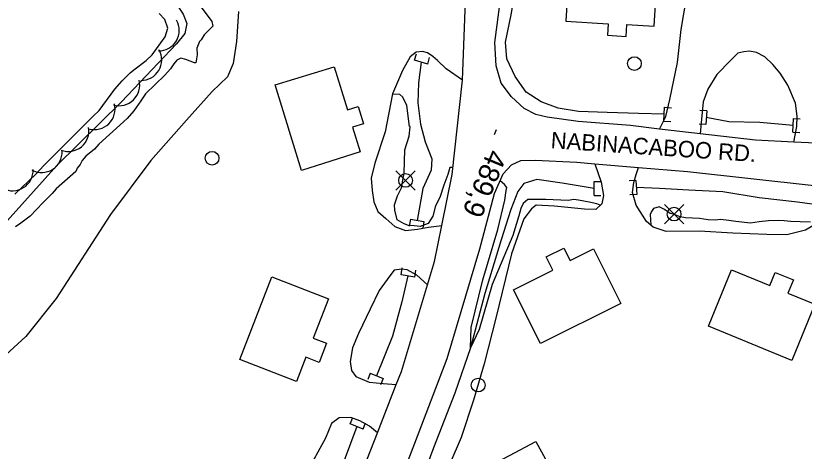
# Model space of a CAD drawing. Extents: x 642515 to 647219, y 6080136 to 6084356.
# Drawn here: x 643746.7 to 643861.6, y 6081612.4 to 6081675.9 of the extents above; entities that cross this region are included whole.
import ezdxf

# ---------------------------------------------------------------- set-up
doc = ezdxf.new("R2010")
doc.units = 0
for name, color, linetype in [('Level 1', 7, 'Continuous'), ('Level 19', 7, 'Continuous'), ('Level 21', 7, 'Continuous'), ('Level 26', 7, 'Continuous'), ('Level 3', 7, 'Continuous'), ('Level 31', 7, 'Continuous'), ('Level 36', 7, 'Continuous'), ('Level 4', 7, 'Continuous'), ('Level 44', 7, 'Continuous')]:
    doc.layers.add(name, color=color, linetype=linetype)

msp = doc.modelspace()

# ---------------------------------------------------------------- linework, layer by layer
at = {"layer": 'Level 1'}
for points in [[(643773.69, 6081677.13), (643775.24, 6081675.02), (643775.41, 6081674.35), (643774.16, 6081673.1), (643773.69, 6081672.38), (643773.46, 6081672.13), (643773.05, 6081671.13), (643773.11, 6081670.17), (643772.95, 6081669.03), (643772.71, 6081669.01), (643771.47, 6081669.5), (643770.73, 6081669.69), (643770.18, 6081669.41), (643769.7, 6081668.86), (643769.22, 6081668.14), (643768.4, 6081667.2), (643765.6, 6081664.52), (643764.91, 6081663.47), (643763.88, 6081662.03), (643762.91, 6081660.92)], [(643763.89, 6081668), (643765.69, 6081669.37), (643766.56, 6081670.19), (643768.47, 6081672.81), (643768.83, 6081674.09), (643768.42, 6081675.35), (643767.6, 6081676.22)], [(643746.55, 6081649.9), (643748.59, 6081651.81), (643749.61, 6081652.8), (643750.78, 6081654.04), (643757.94, 6081661.2), (643758.85, 6081662.07), (643761.14, 6081665.2), (643762.18, 6081666.4), (643763.35, 6081667.56), (643763.89, 6081668)], [(643810.39, 6081653.75), (643809.96, 6081653.75), (643809.65, 6081652.73), (643809.65, 6081652.73), (643809.07, 6081651.2), (643808.47, 6081649.39), (643807.87, 6081648.18), (643807.45, 6081646.67), (643806.8, 6081645.58), (643805.62, 6081645.17), (643804.76, 6081645.24), (643803.91, 6081645.3), (643803.29, 6081645.55), (643802.29, 6081646.12), (643801.95, 6081647.55), (643801.86, 6081648.31), (643802.33, 6081649.63), (643802.9, 6081650.8), (643803.04, 6081651.65), (643803.27, 6081652.96), (643803.36, 6081656.35), (643804.03, 6081658.32), (643804.18, 6081659.7), (643804.1, 6081659.78), (643804.06, 6081659.74), (643804.06, 6081659.74), (643803.68, 6081662.79), (643803.09, 6081664), (643802.66, 6081664.38), (643801.6, 6081664.44)], [(643762.91, 6081660.92), (643758.81, 6081657.18), (643758.14, 6081656.41), (643756.88, 6081655.4), (643756.35, 6081654.8), (643756.07, 6081654.22), (643755.66, 6081653.67), (643755.46, 6081653.17), (643752.57, 6081650.65), (643751.97, 6081649.96), (643750.61, 6081648.59), (643748.77, 6081646.65), (643747.43, 6081645.64), (643746.66, 6081645.1)], [(643831.85, 6081648.25), (643831.35, 6081648.49), (643830.26, 6081648.71), (643828.68, 6081648.98), (643828.03, 6081649.11), (643827.19, 6081648.94), (643823.93, 6081649.12), (643821.32, 6081649.1), (643820.63, 6081648.5), (643820.31, 6081647.81), (643820.01, 6081646.71), (643819.13, 6081643.87), (643816.09, 6081636.72), (643814.21, 6081630.15), (643812.95, 6081627.48), (643813.07, 6081630.47), (643814.73, 6081637.39), (643816.94, 6081644.74), (643817.94, 6081648.99), (643818.14, 6081650.4), (643818.23, 6081650.84), (643817.89, 6081651.3), (643817.26, 6081651.82)], [(643862.51, 6081645.79), (643860.98, 6081645.86), (643859.65, 6081645.91), (643858.64, 6081645.98), (643857.79, 6081646.05), (643856.39, 6081646.01), (643855.03, 6081645.86), (643853.76, 6081645.63), (643851.62, 6081645.87), (643850.61, 6081646.02), (643849.39, 6081646.19), (643848.6, 6081646.07), (643847.59, 6081646.13), (643846.33, 6081646.35), (643844.28, 6081646.43), (643843.51, 6081646.59), (643842.52, 6081646.94), (643842.04, 6081647.07), (643841.2, 6081647.66), (643840.45, 6081648.02), (643839.63, 6081647.78), (643839.33, 6081647.36), (643839.15, 6081646.91), (643839.22, 6081645.37)]]:
    msp.add_lwpolyline(points, dxfattribs=at)
at = {"layer": 'Level 19'}
for points in [[(643840.47, 6081659.37), (643841.42, 6081661.21), (643842, 6081663.68), (643843.11, 6081669.05), (643843.63, 6081673.87), (643844.99, 6081681.94), (643844.7, 6081684.04), (643843.8, 6081685.53), (643842.68, 6081687.3), (643841.28, 6081688.24), (643831.36, 6081688.96), (643826.94, 6081689.45), (643823.42, 6081690.44), (643820.86, 6081690.5), (643818.61, 6081690.11)], [(643779.14, 6081676.5), (643778.87, 6081672.12), (643778.35, 6081668.93), (643777.55, 6081666.98), (643775.31, 6081664.85), (643771.58, 6081660.68), (643766.36, 6081654.8), (643760.5, 6081646.9), (643752.59, 6081634.66), (643748.15, 6081629.15), (643742.83, 6081624.28)], [(643811.78, 6081666.49), (643809.4, 6081668.14), (643808.15, 6081669.33), (643807.47, 6081669.95), (643806.7, 6081670.47), (643805.96, 6081670.68), (643805.03, 6081670.59), (643804.18, 6081669.89), (643803.03, 6081667.92), (643801.61, 6081664.52), (643800.5, 6081658.94), (643799.03, 6081654.4), (643798.48, 6081652.22), (643798.64, 6081650.41), (643798.87, 6081648.77), (643799.45, 6081647.36), (643800.61, 6081646.34), (643801.94, 6081645.18), (643803.47, 6081644.59), (643805.24, 6081644.79), (643806.84, 6081645.06), (643808.78, 6081645.29)], [(643860.05, 6081657.46), (643860.49, 6081659.76), (643860.56, 6081661.23), (643860.33, 6081663.12), (643859.2, 6081665.74), (643858.08, 6081667.5), (643857.03, 6081668.75), (643855.82, 6081669.9), (643854.61, 6081670.52), (643853.62, 6081670.71), (643852.77, 6081670.63), (643851.89, 6081670.42), (643850.89, 6081669.39), (643848.86, 6081667.29), (643847.53, 6081665.19), (643846.86, 6081663.32), (643846.61, 6081660.79), (643846.42, 6081658.67)], [(643831.06, 6081654.31), (643831.99, 6081651.64), (643832.31, 6081649.67), (643832.1, 6081648.48), (643831.21, 6081647.66), (643829.54, 6081647.7), (643825.17, 6081648.15), (643822.52, 6081648.29), (643821.82, 6081647.76), (643820.73, 6081646.29), (643818.93, 6081641.16), (643816.67, 6081632), (643814.94, 6081625.17), (643813.39, 6081619.86), (643811.57, 6081614.41), (643808.28, 6081606.76), (643804.43, 6081597.87), (643804.66, 6081596.92), (643806.77, 6081595.44), (643811, 6081593.71), (643811.46, 6081592.93), (643811.16, 6081591.9), (643810.23, 6081590.75), (643809.32, 6081589.72)], [(643865.37, 6081651.01), (643865.78, 6081648.19), (643865.41, 6081646.91), (643864.16, 6081646.03), (643861.76, 6081644.65), (643859.04, 6081643.93), (643856.11, 6081644.02), (643851.19, 6081644.2), (643846.29, 6081644.5), (643841.46, 6081644.44), (643839.56, 6081645.07), (643838.61, 6081645.91), (643837.09, 6081648.26), (643836.58, 6081650.1), (643836.73, 6081651.57), (643837.07, 6081652.72), (643837.45, 6081653.77)], [(643806.68, 6081636.64), (643805.14, 6081638.07), (643803.71, 6081638.86), (643802.89, 6081638.97), (643801.82, 6081638.78), (643801.18, 6081637.97), (643799.63, 6081635.84), (643798.31, 6081633.13), (643796.65, 6081629.59), (643795.78, 6081627.47), (643795.43, 6081625.51), (643795.63, 6081624.19), (643796.22, 6081623.3), (643798.17, 6081622.5), (643800.24, 6081622.27), (643802.12, 6081622.12)], [(643799.39, 6081615.12), (643798.24, 6081616.05), (643796.81, 6081616.85), (643795.49, 6081617.32), (643793.8, 6081617.29), (643792.68, 6081616.45), (643791.81, 6081614.33), (643789.04, 6081609.27), (643786.74, 6081604.39), (643783.98, 6081599.77), (643780.67, 6081594.95), (643777.33, 6081590.45), (643775.5, 6081588.27), (643773.83, 6081586.1), (643773.65, 6081585.12), (643774.07, 6081584.3), (643775.32, 6081583.05), (643777.33, 6081581.97), (643778.54, 6081581.29), (643780.02, 6081580.68)]]:
    msp.add_lwpolyline(points, dxfattribs=at)
at = {"layer": 'Level 21'}
for points in [[(643865.37, 6081657.22), (643860.05, 6081657.46), (643854.49, 6081657.73), (643846.42, 6081658.67), (643840.47, 6081659.37), (643836.28, 6081659.86), (643828.64, 6081660.47), (643824.14, 6081661.11), (643822.45, 6081661.47), (643820.77, 6081662.35), (643818.92, 6081664.08), (643817.42, 6081666.03), (643816.7, 6081668.59), (643816.5, 6081671.98), (643818.01, 6081683.44), (643818.61, 6081690.11), (643818.65, 6081690.54), (643819.05, 6081696.16), (643818.46, 6081698.53), (643817.83, 6081699.85)], [(643797.87, 6081611.24), (643799.39, 6081615.12), (643802.12, 6081622.12), (643802.88, 6081624.05), (643806.68, 6081636.64), (643807.71, 6081640.04), (643808.78, 6081645.29), (643810.28, 6081652.73), (643811.78, 6081666.49), (643812.32, 6081680.59)], [(643799.89, 6081600.73), (643804.86, 6081613.58), (643809.53, 6081625.93), (643814.33, 6081641.89), (643816.46, 6081649.98), (643817.71, 6081652.85), (643818.94, 6081654.14), (643820.28, 6081654.78), (643822.39, 6081654.81), (643828.46, 6081654.53), (643831.06, 6081654.31), (643837.45, 6081653.77), (643844.59, 6081653.17), (643863.04, 6081651.13), (643865.37, 6081651.01), (643870.32, 6081650.76), (643875.43, 6081650.5), (643880.19, 6081651.08), (643883.4, 6081652.35), (643884.94, 6081653.2)]]:
    msp.add_lwpolyline(points, dxfattribs=at)
at = {"layer": 'Level 26'}
for p, q in [((643804.78, 6081669.39), (643805.06, 6081670.35)), ((643806.72, 6081668.83), (643804.78, 6081669.39)), ((643806.72, 6081668.83), (643807, 6081669.79)), ((643841.12, 6081660.51), (643841.24, 6081662.53)), ((643841.24, 6081662.53), (643842.24, 6081662.47)), ((643847.37, 6081662.03), (643846.39, 6081662.09)), ((643847.37, 6081662.03), (643847.23, 6081660.01)), ((643841.12, 6081660.51), (643842.12, 6081660.45)), ((643847.23, 6081660.01), (643846.25, 6081660.09)), ((643859.92, 6081658.89), (643860, 6081660.91)), ((643860, 6081660.91), (643861, 6081660.87)), ((643859.92, 6081658.89), (643860.92, 6081658.85)), ((643837.06, 6081651.86), (643836.06, 6081651.8)), ((643837.06, 6081651.86), (643837.18, 6081649.84)), ((643830.95, 6081649.69), (643830.95, 6081651.71)), ((643830.95, 6081651.71), (643831.95, 6081651.71)), ((643830.95, 6081649.69), (643831.95, 6081649.69)), ((643837.18, 6081649.84), (643836.18, 6081649.78)), ((643804.19, 6081646.21), (643804.03, 6081645.21)), ((643804.19, 6081646.21), (643806.17, 6081645.89)), ((643806.17, 6081645.89), (643806.03, 6081644.91)), ((643802.84, 6081638.12), (643803, 6081639.12)), ((643804.82, 6081637.8), (643802.84, 6081638.12)), ((643804.82, 6081637.8), (643804.98, 6081638.78)), ((643798.35, 6081623.78), (643797.97, 6081622.86)), ((643798.35, 6081623.78), (643800.21, 6081623.02)), ((643800.21, 6081623.02), (643799.83, 6081622.08)), ((643795.43, 6081616.39), (643795.81, 6081617.33)), ((643797.29, 6081615.63), (643795.43, 6081616.39)), ((643797.29, 6081615.63), (643797.67, 6081616.55))]:
    msp.add_line(p, q, dxfattribs=at)
at = {"layer": 'Level 3'}
msp.add_line((643816.7, 6081659.24), (643816.39, 6081658.5), dxfattribs=at)
at = {"layer": 'Level 31'}
for points in [[(643840.26, 6081683.16), (643827.4, 6081683.98), (643826.83, 6081675.11), (643833.03, 6081674.71), (643832.92, 6081673.03), (643835.64, 6081672.86), (643835.75, 6081674.6), (643839.7, 6081674.35), (643840.26, 6081683.16)], [(643788.32, 6081653.34), (643784.5, 6081665.79), (643793.1, 6081668.43), (643795.02, 6081662.18), (643796.56, 6081662.65), (643797.34, 6081660.12), (643795.78, 6081659.63), (643796.88, 6081656.04), (643788.32, 6081653.34)], [(643834.87, 6081633.95), (643823.15, 6081628.1), (643819.24, 6081635.94), (643824.94, 6081638.78), (643823.98, 6081640.72), (643826.56, 6081642.01), (643827.46, 6081640.21), (643830.89, 6081641.92), (643834.87, 6081633.95)], [(643859.77, 6081625.65), (643847.62, 6081630.65), (643850.99, 6081638.83), (643856.55, 6081636.55), (643857.34, 6081638.48), (643860, 6081637.38), (643859.21, 6081635.46), (643863.13, 6081633.84), (643859.77, 6081625.65)], [(643779.35, 6081625.77), (643784.02, 6081637.83), (643792.27, 6081634.63), (643790.04, 6081628.89), (643791.98, 6081628.14), (643790.91, 6081625.36), (643788.94, 6081626.12), (643787.58, 6081622.6), (643779.35, 6081625.77)], [(643822.49, 6081613.84), (643828.69, 6081602.45), (643820.95, 6081598.24), (643819.02, 6081601.79), (643817.17, 6081600.78), (643815.66, 6081603.56), (643817.57, 6081604.61), (643814.78, 6081609.74), (643822.49, 6081613.84)]]:
    msp.add_lwpolyline(points, dxfattribs=at)
at = {"layer": 'Level 36'}
for p, q in [((643804.91, 6081650.47), (643802.09, 6081653.29)), ((643802.09, 6081650.47), (643804.91, 6081653.29)), ((643844.02, 6081645.57), (643841.2, 6081648.39)), ((643841.2, 6081645.57), (643844.02, 6081648.39))]:
    msp.add_line(p, q, dxfattribs=at)
for centre in [(643836.84, 6081668.9), (643775.3, 6081655.11), (643803.5, 6081651.88), (643842.61, 6081646.98), (643814.07, 6081622.05)]:
    msp.add_circle(centre, 1, dxfattribs=at)
at = {"layer": 'Level 4'}
for points in [[(643745.43, 6081717.6), (643748.54, 6081710.93), (643751.06, 6081707.13), (643754.55, 6081701.94), (643757.89, 6081696.74), (643763.22, 6081688.88), (643766.83, 6081683.29), (643769, 6081679.27), (643771.1, 6081676.13), (643771.64, 6081674.75), (643771.33, 6081673.27), (643770.1, 6081671.77), (643762.12, 6081663.35), (643752.67, 6081654.03), (643744.12, 6081644.6)], [(643841.18, 6081661.51), (643837.43, 6081661.64), (643832.87, 6081661.8), (643828.71, 6081661.9), (643825.71, 6081662.42), (643823.26, 6081663.31), (643821.06, 6081664.73), (643819.46, 6081667), (643818.25, 6081669.61), (643818.03, 6081672.04), (643818.95, 6081676.27), (643819.88, 6081682.66), (643820.28, 6081687.52), (643820.53, 6081689.83)], [(643805.76, 6081669.11), (643805.37, 6081666.08), (643805.26, 6081663.2), (643805.65, 6081660.09), (643806.33, 6081657.49), (643807.3, 6081655.04), (643807.2, 6081653.37), (643806, 6081650.7), (643805.17, 6081646.05)], [(643859.96, 6081659.89), (643855.09, 6081660.32), (643850.61, 6081660.4), (643847.31, 6081661.03)], [(643830.95, 6081650.69), (643826.31, 6081651.46), (643822.62, 6081651.99), (643820.74, 6081651.44), (643819.84, 6081650.25), (643818.81, 6081647.64), (643817.41, 6081643.22), (643815.06, 6081635.42), (643812.95, 6081627.48), (643810.68, 6081620.9), (643807.57, 6081612.93), (643804.66, 6081605.02), (643801.79, 6081598.98), (643801.29, 6081597.37), (643801.63, 6081595.94), (643802.31, 6081594.81), (643803.71, 6081593.73), (643806.35, 6081592.86), (643808.52, 6081592.4), (643810.08, 6081591.93)], [(643864.47, 6081648.17), (643860.62, 6081648.69), (643855.01, 6081649.32), (643849.71, 6081650.21), (643844.78, 6081650.47), (643840.49, 6081650.68), (643837.12, 6081650.86)], [(643803.84, 6081637.96), (643802.96, 6081634.18), (643801.59, 6081629.16), (643799.27, 6081623.4)], [(643796.37, 6081616.01), (643793.45, 6081608.18), (643790.34, 6081600.3), (643788.16, 6081595.91), (643785.52, 6081591.94), (643782.72, 6081587.87), (643780.16, 6081585.12), (643777.84, 6081582.58)]]:
    msp.add_lwpolyline(points, dxfattribs=at)
at = {"layer": 'Level 44'}
for centre, start, end in [((643767.51, 6081673.75), 269.3263, 29.3042), ((643764.96, 6081669.45), 269.3263, 29.3042), ((643761.75, 6081665.77), 254.1755, 14.1535), ((643758.16, 6081662.29), 254.1755, 14.1535), ((643754.35, 6081659.1), 249.339, 9.3169), ((643750.45, 6081656.03), 242.1321, 2.11), ((643746.22, 6081653.37), 242.1321, 2.11)]:
    msp.add_arc(centre, 3, start, end, dxfattribs=at)

# ---------------------------------------------------------------- texts
at = {"layer": 'Level 21'}
msp.add_text('NABINACABOO RD.', height=2.4, rotation=356.1583, dxfattribs=at).set_placement((643824.59, 6081656.57))
at = {"layer": 'Level 3'}
msp.add_text('489,9', height=3, rotation=247.4612, dxfattribs=at).set_placement((643815.56, 6081656.59))

doc.saveas('drawing.dxf')
